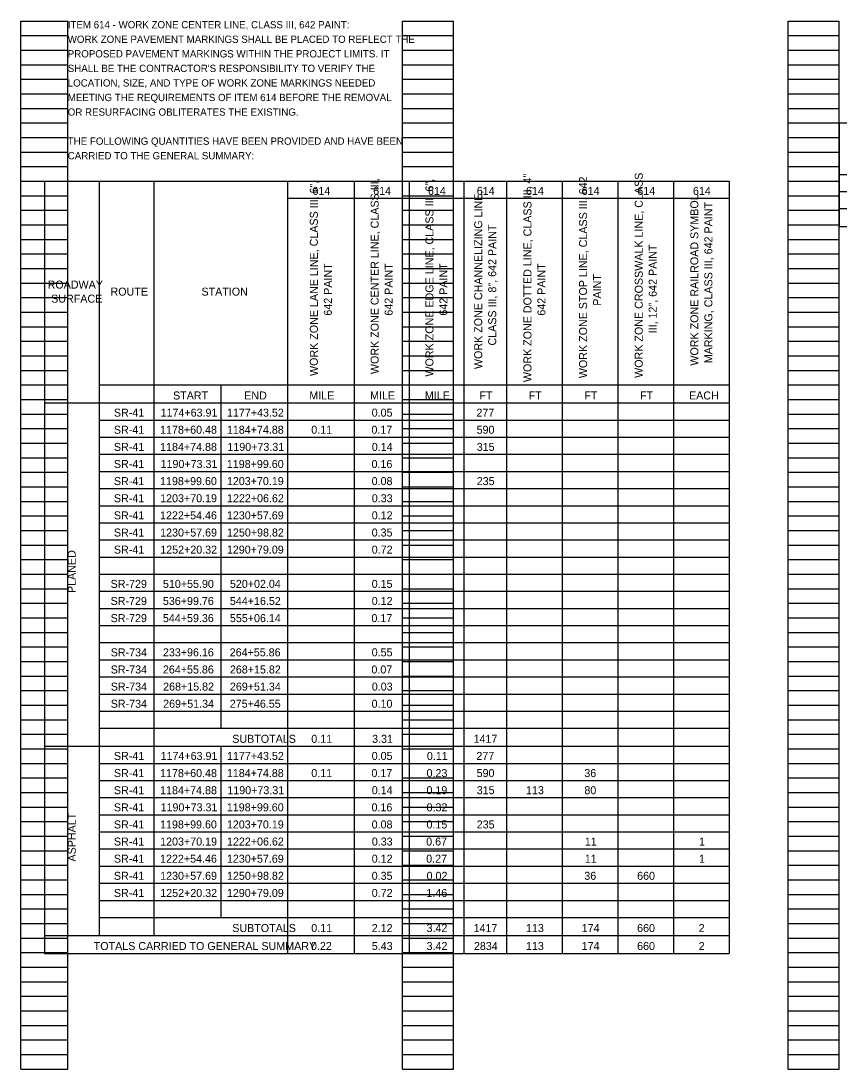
# Model space of a CAD drawing. Extents: x 37613.4 to 37668.4, y 18853.7 to 18946.8.
# Drawn here: x 37637.9 to 37653.64, y 18868.45 to 18888.61 of the extents above; entities that cross this region are included whole.
import ezdxf

# ---------------------------------------------------------------- set-up
doc = ezdxf.new("R2010")
doc.units = 0
doc.layers.add('SH_Data', color=7, linetype='Continuous')
doc.layers.add('SH_Text', color=7, linetype='Continuous')

msp = doc.modelspace()

# ---------------------------------------------------------------- linework, layer by layer
at = {"layer": 'SH_Data'}
for p, q in [((37637.901, 18868.45), (37637.901, 18888.61)), ((37637.901, 18888.61), (37638.801, 18888.61)), ((37638.801, 18868.45), (37638.801, 18888.61)), ((37645.241, 18868.45), (37645.241, 18888.61)), ((37645.241, 18888.61), (37646.221, 18888.61)), ((37646.221, 18868.45), (37646.221, 18888.61)), ((37652.661, 18868.45), (37652.661, 18888.61)), ((37652.661, 18888.61), (37653.641, 18888.61)), ((37653.641, 18868.45), (37653.641, 18888.61)), ((37637.901, 18888.33), (37638.801, 18888.33)), ((37645.241, 18888.33), (37646.221, 18888.33)), ((37652.661, 18888.33), (37653.641, 18888.33)), ((37637.901, 18888.05), (37638.801, 18888.05)), ((37645.241, 18888.05), (37646.221, 18888.05)), ((37652.661, 18888.05), (37653.641, 18888.05)), ((37637.901, 18887.77), (37638.801, 18887.77)), ((37645.241, 18887.77), (37646.221, 18887.77)), ((37652.661, 18887.77), (37653.641, 18887.77)), ((37637.901, 18887.49), (37638.801, 18887.49)), ((37645.241, 18887.49), (37646.221, 18887.49)), ((37652.661, 18887.49), (37653.641, 18887.49)), ((37637.901, 18887.21), (37638.801, 18887.21)), ((37645.241, 18887.21), (37646.221, 18887.21)), ((37652.661, 18887.21), (37653.641, 18887.21)), ((37637.901, 18886.93), (37638.801, 18886.93)), ((37645.241, 18886.93), (37646.221, 18886.93)), ((37652.661, 18886.93), (37653.641, 18886.93)), ((37637.901, 18886.65), (37638.801, 18886.65)), ((37645.241, 18886.65), (37646.221, 18886.65)), ((37652.661, 18886.65), (37653.641, 18886.65)), ((37637.901, 18886.37), (37638.801, 18886.37)), ((37645.241, 18886.37), (37646.221, 18886.37)), ((37652.661, 18886.37), (37653.641, 18886.37)), ((37637.901, 18886.09), (37638.801, 18886.09)), ((37645.241, 18886.09), (37646.221, 18886.09)), ((37652.661, 18886.09), (37653.641, 18886.09)), ((37637.901, 18885.81), (37638.801, 18885.81)), ((37645.241, 18885.81), (37646.221, 18885.81)), ((37652.661, 18885.81), (37653.641, 18885.81)), ((37637.901, 18885.53), (37638.801, 18885.53)), ((37645.241, 18885.53), (37646.221, 18885.53)), ((37652.661, 18885.53), (37653.641, 18885.53)), ((37637.901, 18885.25), (37638.801, 18885.25)), ((37645.241, 18885.25), (37646.221, 18885.25)), ((37652.661, 18885.25), (37653.641, 18885.25)), ((37637.901, 18884.97), (37638.801, 18884.97)), ((37645.241, 18884.97), (37646.221, 18884.97)), ((37652.661, 18884.97), (37653.641, 18884.97)), ((37637.901, 18884.69), (37638.801, 18884.69)), ((37645.241, 18884.69), (37646.221, 18884.69)), ((37652.661, 18884.69), (37653.641, 18884.69)), ((37637.901, 18884.41), (37638.801, 18884.41)), ((37645.241, 18884.41), (37646.221, 18884.41)), ((37652.661, 18884.41), (37653.641, 18884.41)), ((37637.901, 18884.13), (37638.801, 18884.13)), ((37645.241, 18884.13), (37646.221, 18884.13)), ((37652.661, 18884.13), (37653.641, 18884.13)), ((37637.901, 18883.85), (37638.801, 18883.85)), ((37645.241, 18883.85), (37646.221, 18883.85)), ((37652.661, 18883.85), (37653.641, 18883.85)), ((37637.901, 18883.57), (37638.801, 18883.57)), ((37645.241, 18883.57), (37646.221, 18883.57)), ((37652.661, 18883.57), (37653.641, 18883.57)), ((37637.901, 18883.29), (37638.801, 18883.29)), ((37645.241, 18883.29), (37646.221, 18883.29)), ((37652.661, 18883.29), (37653.641, 18883.29)), ((37637.901, 18883.01), (37638.801, 18883.01)), ((37645.241, 18883.01), (37646.221, 18883.01)), ((37652.661, 18883.01), (37653.641, 18883.01)), ((37637.901, 18882.73), (37638.801, 18882.73)), ((37645.241, 18882.73), (37646.221, 18882.73)), ((37652.661, 18882.73), (37653.641, 18882.73)), ((37637.901, 18882.45), (37638.801, 18882.45)), ((37645.241, 18882.45), (37646.221, 18882.45)), ((37652.661, 18882.45), (37653.641, 18882.45)), ((37637.901, 18882.17), (37638.801, 18882.17)), ((37645.241, 18882.17), (37646.221, 18882.17)), ((37652.661, 18882.17), (37653.641, 18882.17)), ((37637.901, 18881.89), (37638.801, 18881.89)), ((37645.241, 18881.89), (37646.221, 18881.89)), ((37652.661, 18881.89), (37653.641, 18881.89)), ((37637.901, 18881.61), (37638.801, 18881.61)), ((37645.241, 18881.61), (37646.221, 18881.61)), ((37652.661, 18881.61), (37653.641, 18881.61)), ((37637.901, 18881.33), (37638.801, 18881.33)), ((37645.241, 18881.33), (37646.221, 18881.33)), ((37652.661, 18881.33), (37653.641, 18881.33)), ((37637.901, 18881.05), (37638.801, 18881.05)), ((37645.241, 18881.05), (37646.221, 18881.05)), ((37652.661, 18881.05), (37653.641, 18881.05)), ((37637.901, 18880.77), (37638.801, 18880.77)), ((37645.241, 18880.77), (37646.221, 18880.77)), ((37652.661, 18880.77), (37653.641, 18880.77)), ((37637.901, 18880.49), (37638.801, 18880.49)), ((37645.241, 18880.49), (37646.221, 18880.49)), ((37652.661, 18880.49), (37653.641, 18880.49)), ((37637.901, 18880.21), (37638.801, 18880.21)), ((37645.241, 18880.21), (37646.221, 18880.21)), ((37652.661, 18880.21), (37653.641, 18880.21)), ((37637.901, 18879.93), (37638.801, 18879.93)), ((37645.241, 18879.93), (37646.221, 18879.93)), ((37652.661, 18879.93), (37653.641, 18879.93)), ((37637.901, 18879.65), (37638.801, 18879.65)), ((37645.241, 18879.65), (37646.221, 18879.65)), ((37652.661, 18879.65), (37653.641, 18879.65)), ((37637.901, 18879.37), (37638.801, 18879.37)), ((37645.241, 18879.37), (37646.221, 18879.37)), ((37652.661, 18879.37), (37653.641, 18879.37)), ((37637.901, 18879.09), (37638.801, 18879.09)), ((37645.241, 18879.09), (37646.221, 18879.09)), ((37652.661, 18879.09), (37653.641, 18879.09)), ((37637.901, 18878.81), (37638.801, 18878.81)), ((37645.241, 18878.81), (37646.221, 18878.81)), ((37652.661, 18878.81), (37653.641, 18878.81)), ((37637.901, 18878.53), (37638.801, 18878.53)), ((37645.241, 18878.53), (37646.221, 18878.53)), ((37652.661, 18878.53), (37653.641, 18878.53)), ((37637.901, 18878.25), (37638.801, 18878.25)), ((37645.241, 18878.25), (37646.221, 18878.25)), ((37652.661, 18878.25), (37653.641, 18878.25)), ((37637.901, 18877.97), (37638.801, 18877.97)), ((37645.241, 18877.97), (37646.221, 18877.97)), ((37652.661, 18877.97), (37653.641, 18877.97)), ((37637.901, 18877.69), (37638.801, 18877.69)), ((37645.241, 18877.69), (37646.221, 18877.69)), ((37652.661, 18877.69), (37653.641, 18877.69)), ((37637.901, 18877.41), (37638.801, 18877.41)), ((37645.241, 18877.41), (37646.221, 18877.41)), ((37652.661, 18877.41), (37653.641, 18877.41)), ((37637.901, 18877.13), (37638.801, 18877.13)), ((37645.241, 18877.13), (37646.221, 18877.13)), ((37652.661, 18877.13), (37653.641, 18877.13)), ((37637.901, 18876.85), (37638.801, 18876.85)), ((37645.241, 18876.85), (37646.221, 18876.85)), ((37652.661, 18876.85), (37653.641, 18876.85)), ((37637.901, 18876.57), (37638.801, 18876.57)), ((37645.241, 18876.57), (37646.221, 18876.57)), ((37652.661, 18876.57), (37653.641, 18876.57)), ((37637.901, 18876.29), (37638.801, 18876.29)), ((37645.241, 18876.29), (37646.221, 18876.29)), ((37652.661, 18876.29), (37653.641, 18876.29)), ((37637.901, 18876.01), (37638.801, 18876.01)), ((37645.241, 18876.01), (37646.221, 18876.01)), ((37652.661, 18876.01), (37653.641, 18876.01)), ((37637.901, 18875.73), (37638.801, 18875.73)), ((37645.241, 18875.73), (37646.221, 18875.73)), ((37652.661, 18875.73), (37653.641, 18875.73)), ((37637.901, 18875.45), (37638.801, 18875.45)), ((37645.241, 18875.45), (37646.221, 18875.45)), ((37652.661, 18875.45), (37653.641, 18875.45)), ((37637.901, 18875.17), (37638.801, 18875.17)), ((37645.241, 18875.17), (37646.221, 18875.17)), ((37652.661, 18875.17), (37653.641, 18875.17)), ((37637.901, 18874.89), (37638.801, 18874.89)), ((37645.241, 18874.89), (37646.221, 18874.89)), ((37652.661, 18874.89), (37653.641, 18874.89)), ((37637.901, 18874.61), (37638.801, 18874.61)), ((37645.241, 18874.61), (37646.221, 18874.61)), ((37652.661, 18874.61), (37653.641, 18874.61)), ((37637.901, 18874.33), (37638.801, 18874.33)), ((37645.241, 18874.33), (37646.221, 18874.33)), ((37652.661, 18874.33), (37653.641, 18874.33)), ((37637.901, 18874.05), (37638.801, 18874.05)), ((37645.241, 18874.05), (37646.221, 18874.05)), ((37652.661, 18874.05), (37653.641, 18874.05)), ((37637.901, 18873.77), (37638.801, 18873.77)), ((37645.241, 18873.77), (37646.221, 18873.77)), ((37652.661, 18873.77), (37653.641, 18873.77)), ((37637.901, 18873.49), (37638.801, 18873.49)), ((37645.241, 18873.49), (37646.221, 18873.49)), ((37652.661, 18873.49), (37653.641, 18873.49)), ((37637.901, 18873.21), (37638.801, 18873.21)), ((37645.241, 18873.21), (37646.221, 18873.21)), ((37652.661, 18873.21), (37653.641, 18873.21)), ((37637.901, 18872.93), (37638.801, 18872.93)), ((37645.241, 18872.93), (37646.221, 18872.93)), ((37652.661, 18872.93), (37653.641, 18872.93)), ((37637.901, 18872.65), (37638.801, 18872.65)), ((37645.241, 18872.65), (37646.221, 18872.65)), ((37652.661, 18872.65), (37653.641, 18872.65)), ((37637.901, 18872.37), (37638.801, 18872.37)), ((37645.241, 18872.37), (37646.221, 18872.37)), ((37652.661, 18872.37), (37653.641, 18872.37)), ((37637.901, 18872.09), (37638.801, 18872.09)), ((37645.241, 18872.09), (37646.221, 18872.09)), ((37652.661, 18872.09), (37653.641, 18872.09)), ((37637.901, 18871.81), (37638.801, 18871.81)), ((37645.241, 18871.81), (37646.221, 18871.81)), ((37652.661, 18871.81), (37653.641, 18871.81)), ((37637.901, 18871.53), (37638.801, 18871.53)), ((37645.241, 18871.53), (37646.221, 18871.53)), ((37652.661, 18871.53), (37653.641, 18871.53)), ((37637.901, 18871.25), (37638.801, 18871.25)), ((37645.241, 18871.25), (37646.221, 18871.25)), ((37652.661, 18871.25), (37653.641, 18871.25)), ((37637.901, 18870.97), (37638.801, 18870.97)), ((37645.241, 18870.97), (37646.221, 18870.97)), ((37652.661, 18870.97), (37653.641, 18870.97)), ((37637.901, 18870.69), (37638.801, 18870.69)), ((37645.241, 18870.69), (37646.221, 18870.69)), ((37652.661, 18870.69), (37653.641, 18870.69)), ((37637.901, 18870.41), (37638.801, 18870.41)), ((37645.241, 18870.41), (37646.221, 18870.41)), ((37652.661, 18870.41), (37653.641, 18870.41)), ((37637.901, 18870.13), (37638.801, 18870.13)), ((37645.241, 18870.13), (37646.221, 18870.13)), ((37652.661, 18870.13), (37653.641, 18870.13)), ((37637.901, 18869.85), (37638.801, 18869.85)), ((37645.241, 18869.85), (37646.221, 18869.85)), ((37652.661, 18869.85), (37653.641, 18869.85)), ((37637.901, 18869.57), (37638.801, 18869.57)), ((37645.241, 18869.57), (37646.221, 18869.57)), ((37652.661, 18869.57), (37653.641, 18869.57)), ((37637.901, 18869.29), (37638.801, 18869.29)), ((37645.241, 18869.29), (37646.221, 18869.29)), ((37652.661, 18869.29), (37653.641, 18869.29)), ((37637.901, 18869.01), (37638.801, 18869.01)), ((37645.241, 18869.01), (37646.221, 18869.01)), ((37652.661, 18869.01), (37653.641, 18869.01)), ((37637.901, 18868.73), (37638.801, 18868.73)), ((37645.241, 18868.73), (37646.221, 18868.73)), ((37652.661, 18868.73), (37653.641, 18868.73)), ((37637.901, 18868.45), (37638.801, 18868.45)), ((37645.241, 18868.45), (37646.221, 18868.45)), ((37652.661, 18868.45), (37653.641, 18868.45))]:
    msp.add_line(p, q, dxfattribs=at)
at = {"layer": 'SH_Text'}
for p, q in [((37653.641, 18886.65), (37660.097, 18886.65)), ((37653.641, 18886.65), (37653.641, 18884.657)), ((37653.641, 18885.661), (37660.097, 18885.661)), ((37638.351, 18885.53), (37651.527, 18885.53)), ((37638.351, 18885.53), (37638.351, 18870.673)), ((37639.405, 18885.53), (37639.405, 18871.019)), ((37640.459, 18885.53), (37640.459, 18871.019)), ((37643.029, 18885.53), (37643.029, 18870.673)), ((37644.313, 18885.53), (37644.313, 18870.673)), ((37645.367, 18885.53), (37645.367, 18870.673)), ((37646.422, 18885.53), (37646.422, 18870.673)), ((37647.245, 18885.53), (37647.245, 18870.673)), ((37648.316, 18885.53), (37648.316, 18870.673)), ((37649.386, 18885.53), (37649.386, 18870.673)), ((37650.457, 18885.53), (37650.457, 18870.673)), ((37651.527, 18885.53), (37651.527, 18870.673)), ((37653.641, 18885.332), (37660.097, 18885.332)), ((37643.029, 18885.2), (37651.527, 18885.2)), ((37653.641, 18885.003), (37660.097, 18885.003)), ((37653.641, 18884.657), (37660.097, 18884.657)), ((37639.405, 18881.61), (37651.527, 18881.61)), ((37641.744, 18881.61), (37641.744, 18875.005)), ((37638.351, 18881.264), (37651.527, 18881.264)), ((37639.405, 18880.934), (37651.527, 18880.934)), ((37639.405, 18880.605), (37651.527, 18880.605)), ((37639.405, 18880.276), (37651.527, 18880.276)), ((37639.405, 18879.946), (37651.527, 18879.946)), ((37639.405, 18879.617), (37651.527, 18879.617)), ((37639.405, 18879.287), (37651.527, 18879.287)), ((37639.405, 18878.958), (37651.527, 18878.958)), ((37639.405, 18878.629), (37651.527, 18878.629)), ((37639.405, 18878.299), (37651.527, 18878.299)), ((37639.405, 18877.97), (37651.527, 18877.97)), ((37639.405, 18877.64), (37651.527, 18877.64)), ((37639.405, 18877.311), (37651.527, 18877.311)), ((37639.405, 18876.981), (37651.527, 18876.981)), ((37639.405, 18876.652), (37651.527, 18876.652)), ((37639.405, 18876.323), (37651.527, 18876.323)), ((37639.405, 18875.993), (37651.527, 18875.993)), ((37639.405, 18875.664), (37651.527, 18875.664)), ((37639.405, 18875.334), (37651.527, 18875.334)), ((37639.405, 18875.005), (37651.527, 18875.005)), ((37638.351, 18874.659), (37651.527, 18874.659)), ((37641.744, 18874.659), (37641.744, 18871.365)), ((37639.405, 18874.33), (37651.527, 18874.33)), ((37639.405, 18874), (37651.527, 18874)), ((37639.405, 18873.671), (37651.527, 18873.671)), ((37639.405, 18873.341), (37651.527, 18873.341)), ((37639.405, 18873.012), (37651.527, 18873.012)), ((37639.405, 18872.683), (37651.527, 18872.683)), ((37639.405, 18872.353), (37651.527, 18872.353)), ((37639.405, 18872.024), (37651.527, 18872.024)), ((37639.405, 18871.694), (37651.527, 18871.694)), ((37639.405, 18871.365), (37651.527, 18871.365)), ((37638.351, 18871.019), (37651.527, 18871.019)), ((37638.351, 18870.673), (37651.527, 18870.673))]:
    msp.add_line(p, q, dxfattribs=at)

# ---------------------------------------------------------------- texts
for s, height, p in [('ITEM 614 - WORK ZONE CENTER LINE, CLASS III, 642 PAINT:', 0.14, (37638.801, 18888.47)), ('WORK ZONE PAVEMENT MARKINGS SHALL BE PLACED TO REFLECT THE ', 0.14, (37638.801, 18888.19)), ('PROPOSED PAVEMENT MARKINGS WITHIN THE PROJECT LIMITS. IT ', 0.14, (37638.801, 18887.91)), ("SHALL BE THE CONTRACTOR'S RESPONSIBILITY TO VERIFY THE ", 0.14, (37638.801, 18887.63)), ('LOCATION, SIZE, AND TYPE OF WORK ZONE MARKINGS NEEDED ', 0.14, (37638.801, 18887.35)), ('MEETING THE REQUIREMENTS OF ITEM 614 BEFORE THE REMOVAL ', 0.14, (37638.801, 18887.07)), ('OR RESURFACING OBLITERATES THE EXISTING.', 0.14, (37638.801, 18886.79)), ('THE FOLLOWING QUANTITIES HAVE BEEN PROVIDED AND HAVE BEEN ', 0.14, (37638.801, 18886.23)), ('CARRIED TO THE GENERAL SUMMARY:', 0.14, (37638.801, 18885.95)), ('614', 0.154, (37643.509, 18885.266)), ('614', 0.154, (37644.678, 18885.266)), ('614', 0.154, (37645.732, 18885.266)), ('614', 0.154, (37646.671, 18885.266)), ('614', 0.154, (37647.618, 18885.266)), ('614', 0.154, (37648.689, 18885.266)), ('614', 0.154, (37649.76, 18885.266)), ('614', 0.154, (37650.83, 18885.266)), ('ROADWAY ', 0.154, (37638.414, 18883.463)), ('ROUTE', 0.154, (37639.624, 18883.328)), ('STATION', 0.154, (37641.374, 18883.328)), ('SURFACE', 0.154, (37638.482, 18883.193)), ('START', 0.154, (37640.827, 18881.33)), ('END', 0.154, (37642.197, 18881.33)), ('MILE', 0.154, (37643.449, 18881.33)), ('MILE', 0.154, (37644.618, 18881.33)), ('MILE', 0.154, (37645.672, 18881.33)), ('FT', 0.154, (37646.722, 18881.33)), ('FT', 0.154, (37647.669, 18881.33)), ('FT', 0.154, (37648.74, 18881.33)), ('FT', 0.154, (37649.811, 18881.33)), ('EACH', 0.154, (37650.755, 18881.33)), ('SR-41', 0.154, (37639.689, 18881)), ('1174+63.91', 0.154, (37640.587, 18881)), ('1177+43.52', 0.154, (37641.865, 18881)), ('0.05', 0.154, (37644.649, 18881)), ('277', 0.154, (37646.664, 18881)), ('SR-41', 0.154, (37639.689, 18880.671)), ('1178+60.48', 0.154, (37640.578, 18880.671)), ('1184+74.88', 0.154, (37641.863, 18880.671)), ('0.11', 0.154, (37643.487, 18880.671)), ('0.17', 0.154, (37644.644, 18880.671)), ('590', 0.154, (37646.668, 18880.671)), ('SR-41', 0.154, (37639.689, 18880.341)), ('1184+74.88', 0.154, (37640.578, 18880.341)), ('1190+73.31', 0.154, (37641.872, 18880.341)), ('0.14', 0.154, (37644.651, 18880.341)), ('315', 0.154, (37646.67, 18880.341)), ('SR-41', 0.154, (37639.689, 18880.012)), ('1190+73.31', 0.154, (37640.587, 18880.012)), ('1198+99.60', 0.154, (37641.862, 18880.012)), ('0.16', 0.154, (37644.646, 18880.012)), ('SR-41', 0.154, (37639.689, 18879.683)), ('1198+99.60', 0.154, (37640.577, 18879.683)), ('1203+70.19', 0.154, (37641.863, 18879.683)), ('0.08', 0.154, (37644.648, 18879.683)), ('235', 0.154, (37646.67, 18879.683)), ('SR-41', 0.154, (37639.689, 18879.353)), ('1203+70.19', 0.154, (37640.579, 18879.353)), ('1222+06.62', 0.154, (37641.865, 18879.353)), ('0.33', 0.154, (37644.651, 18879.353)), ('SR-41', 0.154, (37639.689, 18879.024)), ('1222+54.46', 0.154, (37640.577, 18879.024)), ('1230+57.69', 0.154, (37641.863, 18879.024)), ('0.12', 0.154, (37644.65, 18879.024)), ('SR-41', 0.154, (37639.689, 18878.694)), ('1230+57.69', 0.154, (37640.579, 18878.694)), ('1250+98.82', 0.154, (37641.865, 18878.694)), ('0.35', 0.154, (37644.649, 18878.694)), ('SR-41', 0.154, (37639.689, 18878.365)), ('1252+20.32', 0.154, (37640.581, 18878.365)), ('1290+79.09', 0.154, (37641.863, 18878.365)), ('0.72', 0.154, (37644.65, 18878.365)), ('SR-729', 0.154, (37639.626, 18877.706)), ('510+55.90', 0.154, (37640.633, 18877.706)), ('520+02.04', 0.154, (37641.921, 18877.706)), ('0.15', 0.154, (37644.649, 18877.706)), ('SR-729', 0.154, (37639.626, 18877.377)), ('536+99.76', 0.154, (37640.632, 18877.377)), ('544+16.52', 0.154, (37641.921, 18877.377)), ('0.12', 0.154, (37644.65, 18877.377)), ('SR-729', 0.154, (37639.626, 18877.047)), ('544+59.36', 0.154, (37640.632, 18877.047)), ('555+06.14', 0.154, (37641.921, 18877.047)), ('0.17', 0.154, (37644.644, 18877.047)), ('SR-734', 0.154, (37639.628, 18876.389)), ('233+96.16', 0.154, (37640.632, 18876.389)), ('264+55.86', 0.154, (37641.917, 18876.389)), ('0.55', 0.154, (37644.649, 18876.389)), ('SR-734', 0.154, (37639.628, 18876.059)), ('264+55.86', 0.154, (37640.632, 18876.059)), ('268+15.82', 0.154, (37641.921, 18876.059)), ('0.07', 0.154, (37644.644, 18876.059)), ('SR-734', 0.154, (37639.628, 18875.73)), ('268+15.82', 0.154, (37640.636, 18875.73)), ('269+51.34', 0.154, (37641.921, 18875.73)), ('0.03', 0.154, (37644.651, 18875.73)), ('SR-734', 0.154, (37639.628, 18875.4)), ('269+51.34', 0.154, (37640.636, 18875.4)), ('275+46.55', 0.154, (37641.919, 18875.4)), ('0.10', 0.154, (37644.647, 18875.4)), ('SUBTOTALS', 0.154, (37641.966, 18874.725)), ('0.11', 0.154, (37643.487, 18874.725)), ('3.31', 0.154, (37644.657, 18874.725)), ('1417', 0.154, (37646.609, 18874.725)), ('SR-41', 0.154, (37639.689, 18874.396)), ('1174+63.91', 0.154, (37640.587, 18874.396)), ('1177+43.52', 0.154, (37641.865, 18874.396)), ('0.05', 0.154, (37644.649, 18874.396)), ('0.11', 0.154, (37645.711, 18874.396)), ('277', 0.154, (37646.664, 18874.396)), ('SR-41', 0.154, (37639.689, 18874.066)), ('1178+60.48', 0.154, (37640.578, 18874.066)), ('1184+74.88', 0.154, (37641.863, 18874.066)), ('0.11', 0.154, (37643.487, 18874.066)), ('0.17', 0.154, (37644.644, 18874.066)), ('0.23', 0.154, (37645.705, 18874.066)), ('590', 0.154, (37646.668, 18874.066)), ('36', 0.154, (37648.74, 18874.066)), ('SR-41', 0.154, (37639.689, 18873.737)), ('1184+74.88', 0.154, (37640.578, 18873.737)), ('1190+73.31', 0.154, (37641.872, 18873.737)), ('0.14', 0.154, (37644.651, 18873.737)), ('0.19', 0.154, (37645.703, 18873.737)), ('315', 0.154, (37646.67, 18873.737)), ('113', 0.154, (37647.618, 18873.737)), ('80', 0.154, (37648.741, 18873.737)), ('SR-41', 0.154, (37639.689, 18873.407)), ('1190+73.31', 0.154, (37640.587, 18873.407)), ('1198+99.60', 0.154, (37641.862, 18873.407)), ('0.16', 0.154, (37644.646, 18873.407)), ('0.32', 0.154, (37645.705, 18873.407)), ('SR-41', 0.154, (37639.689, 18873.078)), ('1198+99.60', 0.154, (37640.577, 18873.078)), ('1203+70.19', 0.154, (37641.863, 18873.078)), ('0.08', 0.154, (37644.648, 18873.078)), ('0.15', 0.154, (37645.703, 18873.078)), ('235', 0.154, (37646.67, 18873.078)), ('SR-41', 0.154, (37639.689, 18872.749)), ('1203+70.19', 0.154, (37640.579, 18872.749)), ('1222+06.62', 0.154, (37641.865, 18872.749)), ('0.33', 0.154, (37644.651, 18872.749)), ('0.67', 0.154, (37645.698, 18872.749)), ('11', 0.154, (37648.75, 18872.749)), ('1', 0.154, (37650.947, 18872.749)), ('SR-41', 0.154, (37639.689, 18872.419)), ('1222+54.46', 0.154, (37640.577, 18872.419)), ('1230+57.69', 0.154, (37641.863, 18872.419)), ('0.12', 0.154, (37644.65, 18872.419)), ('0.27', 0.154, (37645.698, 18872.419)), ('11', 0.154, (37648.75, 18872.419)), ('1', 0.154, (37650.947, 18872.419)), ('SR-41', 0.154, (37639.689, 18872.09)), ('1230+57.69', 0.154, (37640.579, 18872.09)), ('1250+98.82', 0.154, (37641.865, 18872.09)), ('0.35', 0.154, (37644.649, 18872.09)), ('0.02', 0.154, (37645.705, 18872.09)), ('36', 0.154, (37648.74, 18872.09)), ('660', 0.154, (37649.756, 18872.09)), ('SR-41', 0.154, (37639.689, 18871.76)), ('1252+20.32', 0.154, (37640.581, 18871.76)), ('1290+79.09', 0.154, (37641.863, 18871.76)), ('0.72', 0.154, (37644.65, 18871.76)), ('1.46', 0.154, (37645.701, 18871.76)), ('SUBTOTALS', 0.154, (37641.966, 18871.085)), ('0.11', 0.154, (37643.487, 18871.085)), ('2.12', 0.154, (37644.65, 18871.085)), ('3.42', 0.154, (37645.705, 18871.085)), ('1417', 0.154, (37646.609, 18871.085)), ('113', 0.154, (37647.618, 18871.085)), ('174', 0.154, (37648.689, 18871.085)), ('660', 0.154, (37649.756, 18871.085)), ('2', 0.154, (37650.94, 18871.085)), ('TOTALS CARRIED TO GENERAL SUMMARY', 0.154, (37639.301, 18870.739)), ('0.22', 0.154, (37643.481, 18870.739)), ('5.43', 0.154, (37644.651, 18870.739)), ('3.42', 0.154, (37645.705, 18870.739)), ('2834', 0.154, (37646.616, 18870.739)), ('113', 0.154, (37647.618, 18870.739)), ('174', 0.154, (37648.689, 18870.739)), ('660', 0.154, (37649.756, 18870.739)), ('2', 0.154, (37650.94, 18870.739))]:
    msp.add_text(s, height=height, dxfattribs=at).set_placement(p)
for s, p in [('WORK ZONE DOTTED LINE, CLASS III, 4" ', (37647.723, 18881.664)), ('WORK ZONE CROSSWALK LINE, CLASS ', (37649.864, 18881.746)), ('WORK ZONE LANE LINE, CLASS III, 6", ', (37643.613, 18881.781)), ('WORK ZONE CENTER LINE, CLASS III, ', (37644.783, 18881.818)), ('WORK ZONE EDGE LINE, CLASS III, 6", ', (37645.837, 18881.771)), ('WORK ZONE STOP LINE, CLASS III, 642 ', (37648.793, 18881.74)), ('WORK ZONE CHANNELIZING LINE, ', (37646.776, 18881.915)), ('WORK ZONE RAILROAD SYMBOL ', (37650.934, 18881.981)), ('MARKING, CLASS III, 642 PAINT', (37651.204, 18882.028)), ('CLASS III, 8", 642 PAINT', (37647.045, 18882.368)), ('III, 12", 642 PAINT', (37650.133, 18882.602)), ('642 PAINT', (37643.883, 18882.943)), ('642 PAINT', (37645.052, 18882.943)), ('642 PAINT', (37646.106, 18882.943)), ('642 PAINT', (37647.992, 18882.943)), ('PAINT', (37649.063, 18883.134)), ('PLANED', (37638.955, 18877.607)), ('ASPHALT', (37638.955, 18872.441))]:
    msp.add_text(s, height=0.154, rotation=90, dxfattribs=at).set_placement(p)

doc.saveas('drawing.dxf')
